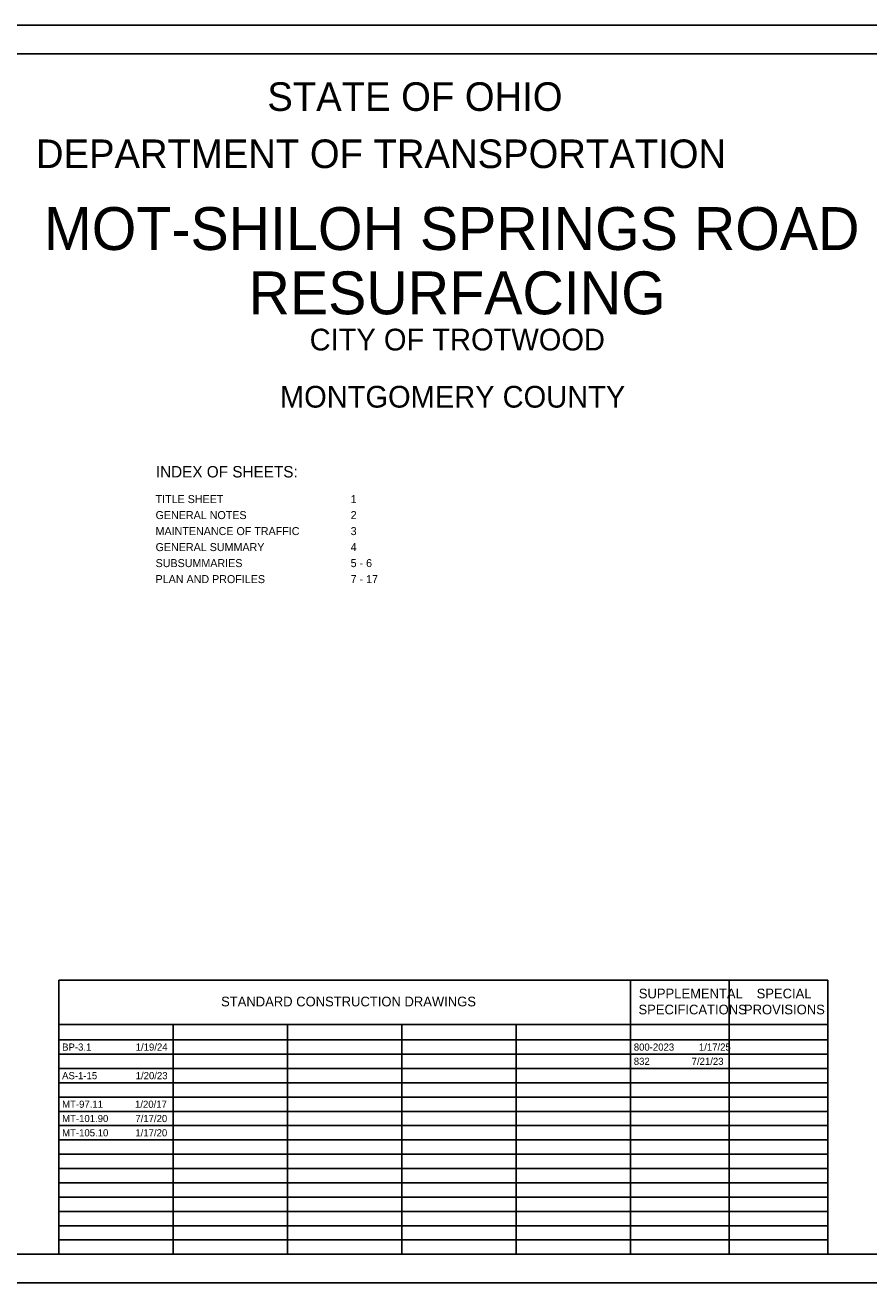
# Model space of a CAD drawing. Extents: x 0 to 42, y 0 to 22.
# Drawn here: x 9.56 to 24.32, y 0 to 22 of the extents above; entities that cross this region are included whole.
import ezdxf

# ---------------------------------------------------------------- set-up
doc = ezdxf.new("R2010")
doc.units = 0
for name, color, linetype in [('GM_X_Adjacent_County', 7, 'Continuous'), ('GM_X_County', 7, 'Continuous'), ('GM_X_Section', 7, 'Continuous'), ('GM_X_Township', 7, 'Continuous')]:
    doc.layers.add(name, color=color, linetype=linetype)

msp = doc.modelspace()

# ---------------------------------------------------------------- linework, layer by layer
at = {"layer": 'GM_X_County'}
msp.add_lwpolyline([(1.5, 21.5), (33.5, 21.5), (33.5, 0.5), (1.5, 0.5)], close=True, dxfattribs=at)
at = {"layer": 'GM_X_Section'}
msp.add_lwpolyline([(0, 0), (34, 0), (34, 22), (0, 22)], close=True, dxfattribs=at)
at = {"layer": 'GM_X_Township'}
for p, q in [((10.15, 5.292), (23.6, 5.292)), ((10.15, 0.5), (10.15, 5.292)), ((20.15, 0.5), (20.15, 5.292)), ((21.875, 0.5), (21.875, 5.292)), ((23.6, 0.5), (23.6, 5.292)), ((10.15, 4.521), (23.6, 4.521)), ((12.15, 0.5), (12.15, 4.521)), ((14.15, 0.5), (14.15, 4.521)), ((16.15, 0.5), (16.15, 4.521)), ((18.15, 0.5), (18.15, 4.521)), ((10.15, 4.25), (23.6, 4.25)), ((10.15, 4), (23.6, 4)), ((10.15, 3.75), (23.6, 3.75)), ((10.15, 3.5), (23.6, 3.5)), ((10.15, 3.25), (23.6, 3.25)), ((10.15, 3), (23.6, 3)), ((10.15, 2.75), (23.6, 2.75)), ((10.15, 2.5), (23.6, 2.5)), ((10.15, 2.25), (23.6, 2.25)), ((10.15, 2), (23.6, 2)), ((10.15, 1.75), (23.6, 1.75)), ((10.15, 1.5), (23.6, 1.5)), ((10.15, 1.25), (23.6, 1.25)), ((10.15, 1), (23.6, 1)), ((10.15, 0.75), (23.6, 0.75))]:
    msp.add_line(p, q, dxfattribs=at)

# ---------------------------------------------------------------- texts
at = {"layer": 'GM_X_Adjacent_County'}
for s, height, p in [('STATE OF OHIO', 0.5, (13.795, 20.5)), ('DEPARTMENT OF TRANSPORTATION', 0.5, (9.747, 19.5)), ('MOT-SHILOH SPRINGS ROAD', 0.75, (9.888, 18.067)), ('RESURFACING', 0.75, (13.465, 16.942)), ('CITY OF TROTWOOD', 0.38, (14.535, 16.31)), ('MONTGOMERY COUNTY', 0.38, (14.015, 15.31)), ('INDEX OF SHEETS:', 0.2, (11.844, 14.088)), ('SUPPLEMENTAL', 0.17, (20.293, 4.976)), ('SPECIAL', 0.17, (22.354, 4.976)), ('STANDARD CONSTRUCTION DRAWINGS', 0.17, (12.986, 4.836)), ('SPECIFICATIONS', 0.17, (20.287, 4.696)), ('PROVISIONS', 0.17, (22.132, 4.696))]:
    msp.add_text(s, height=height, dxfattribs=at).set_placement(p)
at = {"layer": 'GM_X_Township'}
for s, height, p in [('TITLE SHEET', 0.14, (11.84, 13.64)), (' 1', 0.14, (15.2, 13.64)), ('GENERAL NOTES', 0.14, (11.84, 13.36)), (' 2', 0.14, (15.2, 13.36)), ('MAINTENANCE OF TRAFFIC', 0.14, (11.84, 13.08)), (' 3', 0.14, (15.2, 13.08)), ('GENERAL SUMMARY', 0.14, (11.84, 12.8)), (' 4', 0.14, (15.2, 12.8)), ('SUBSUMMARIES', 0.14, (11.84, 12.52)), (' 5 - 6', 0.14, (15.2, 12.52)), ('PLAN AND PROFILES', 0.14, (11.84, 12.24)), (' 7 - 17', 0.14, (15.2, 12.24)), ('BP-3.1', 0.125, (10.205, 4.062)), ('1/19/24', 0.125, (11.492, 4.062)), ('800-2023', 0.125, (20.205, 4.062)), ('1/17/25', 0.125, (21.344, 4.062)), ('832', 0.125, (20.205, 3.812)), ('7/21/23', 0.125, (21.217, 3.812)), ('AS-1-15', 0.125, (10.205, 3.562)), ('1/20/23', 0.125, (11.492, 3.562)), ('MT-97.11', 0.125, (10.205, 3.062)), ('1/20/17', 0.125, (11.48, 3.062)), ('MT-101.90', 0.125, (10.205, 2.812)), ('7/17/20', 0.125, (11.486, 2.812)), ('MT-105.10', 0.125, (10.205, 2.562)), ('1/17/20', 0.125, (11.486, 2.562))]:
    msp.add_text(s, height=height, dxfattribs=at).set_placement(p)

doc.saveas('drawing.dxf')
